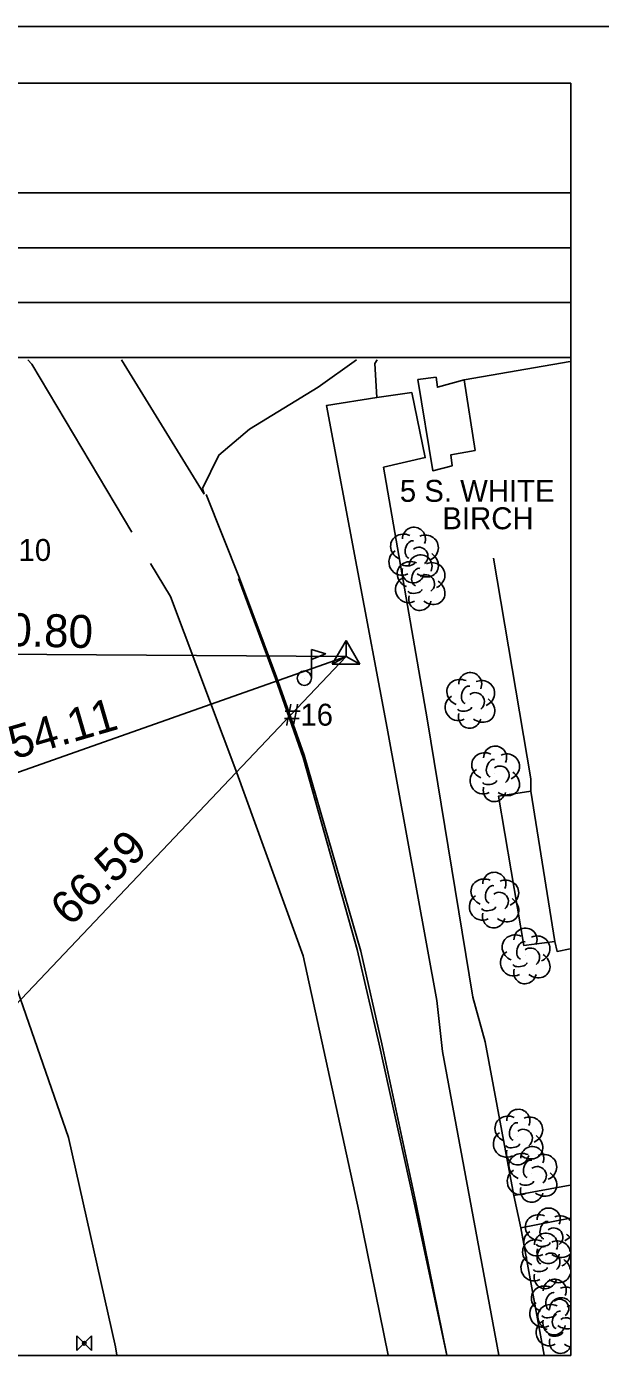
# Model space of a CAD drawing. Extents: x 1603676 to 1604316, y 320315 to 320735.
# Drawn here: x 1603771.3 to 1603823.6, y 320487.1 to 320608.2 of the extents above; entities that cross this region are included whole.
import ezdxf

# ---------------------------------------------------------------- set-up
doc = ezdxf.new("R2010")
doc.units = 0
for name, color, linetype in [('CPSM', 7, 'Continuous'), ('Default', 7, 'Continuous'), ('L_C', 7, 'Continuous'), ('LBC', 7, 'Continuous'), ('LBF', 7, 'Continuous'), ('LDEFAULT', 7, 'Continuous'), ('LMB', 7, 'Continuous'), ('LSH', 7, 'Continuous'), ('LTD', 7, 'Continuous'), ('NBL1', 7, 'Continuous'), ('PET', 7, 'Continuous'), ('PSP', 7, 'Continuous'), ('RC', 7, 'Continuous'), ('RSW', 7, 'Continuous'), ('U_C', 7, 'Continuous'), ('UWV', 7, 'Continuous')]:
    doc.layers.add(name, color=color, linetype=linetype)

msp = doc.modelspace()

# ---------------------------------------------------------------- linework, layer by layer
at = {"layer": 'CPSM'}
for p, q in [((1603799.17, 320550.09), (1603800.42, 320552.25)), ((1603801.67, 320550.09), (1603800.42, 320552.25)), ((1603800.42, 320550.81), (1603800.42, 320552.25)), ((1603799.17, 320550.09), (1603800.42, 320550.81)), ((1603799.17, 320550.09), (1603801.67, 320550.09)), ((1603800.42, 320550.81), (1603800.42, 320550.81)), ((1603800.42, 320550.81), (1603801.67, 320550.09))]:
    msp.add_line(p, q, dxfattribs=at)
at = {"layer": 'LBC'}
msp.add_lwpolyline([(1603820.87, 320524.14), (1603819.67, 320523.9), (1603819.46, 320524.82), (1603817.27, 320538.51), (1603817.28, 320539.65)], dxfattribs=at)
at = {"layer": 'LBF'}
for points in [[(1603812.2, 320569.59), (1603811.2, 320576.02), (1603820.87, 320577.68)], [(1603812.2, 320569.59), (1603809.98, 320569.17), (1603810.09, 320568.19), (1603808.33, 320567.74), (1603806.98, 320576.04), (1603808.64, 320576.26), (1603808.76, 320575.34), (1603811.2, 320576.02)], [(1603817.28, 320539.65), (1603813.86, 320559.76)], [(1603819.46, 320524.82), (1603816.65, 320524.43), (1603814.33, 320538.07), (1603817.27, 320538.51)]]:
    msp.add_lwpolyline(points, dxfattribs=at)
at = {"layer": 'LDEFAULT'}
for q in [(1603739.62, 320551.21), (1603749.41, 320532.76), (1603754.59, 320502.47)]:
    msp.add_line((1603800.42, 320550.81), q, dxfattribs=at)
at = {"layer": 'LMB'}
for p, q in [((1603797.27, 320551.42), (1603798.57, 320551.04)), ((1603797.28, 320548.83), (1603797.28, 320551.43)), ((1603797.28, 320550.53), (1603798.56, 320551.03)), ((1603796.62, 320548.82), (1603796.62, 320548.82))]:
    msp.add_line(p, q, dxfattribs=at)
msp.add_circle((1603796.62, 320548.82), 0.656, dxfattribs=at)
at = {"layer": 'LSH'}
for p, q in [((1603806.57, 320560.09), (1603806.57, 320560.09)), ((1603806.57, 320560.09), (1603806.57, 320560.09)), ((1603813.97, 320540.15), (1603813.97, 320540.15)), ((1603813.97, 320540.15), (1603813.97, 320540.15)), ((1603816.75, 320523.54), (1603816.75, 320523.54)), ((1603816.75, 320523.54), (1603816.75, 320523.54)), ((1603816.09, 320507.03), (1603816.09, 320507.03)), ((1603816.09, 320507.03), (1603816.09, 320507.03)), ((1603817.37, 320503.62), (1603817.37, 320503.62)), ((1603817.37, 320503.62), (1603817.37, 320503.62)), ((1603818.87, 320498.03), (1603818.87, 320498.03)), ((1603818.87, 320498.03), (1603818.87, 320498.03)), ((1603818.61, 320495.74), (1603818.61, 320495.74)), ((1603818.61, 320495.74), (1603818.61, 320495.74)), ((1603819.41, 320491.53), (1603819.41, 320491.53)), ((1603819.41, 320491.53), (1603819.41, 320491.53)), ((1603820, 320489.84), (1603820, 320489.84)), ((1603820, 320489.84), (1603820, 320489.84))]:
    msp.add_line(p, q, dxfattribs=at)
for centre, start in [((1603806.62, 320561.53), 335.5272), ((1603814.02, 320541.58), 335.5272), ((1603816.79, 320524.98), 335.5272), ((1603816.14, 320508.46), 335.5272), ((1603817.41, 320505.06), 335.5272), ((1603818.91, 320499.46), 335.5272), ((1603818.66, 320497.17), 335.5272), ((1603819.46, 320492.96), 335.5272), ((1603820.04, 320491.28), 37.9845)]:
    msp.add_arc(centre, 1.05, start, 180.9563, dxfattribs=at)
for centre, major_axis, ratio, start_param, end_param in [((1603805.78, 320560.76), (1.21, -0.51), 0.895232, 1.570796, 4.712389), ((1603806.37, 320560.55), (-0.208, -0.792), 0.645439, 3.141593, 6.283185), ((1603807.62, 320560.68), (-1.14, -0.48), 0.949671, 1.570796, 4.712389), ((1603805.49, 320559.38), (0.58, -1.04), 0.959034, 3.141593, 6.283185), ((1603807.07, 320559.93), (-0.5, 0.667), 0.989748, 3.141593, 6.283185), ((1603807.57, 320559.26), (-1.09, 0.79), 0.841452, 1.570796, 4.712389), ((1603806.57, 320558.59), (0.26, 1.06), 0.942809, 1.570796, 4.712389), ((1603806.12, 320559.34), (-0.625, -0.083), 0.423636, 0, 3.141593), ((1603813.18, 320540.82), (1.21, -0.51), 0.895232, 1.570796, 4.712389), ((1603815.02, 320540.73), (-1.14, -0.48), 0.949671, 1.570796, 4.712389), ((1603812.89, 320539.44), (0.58, -1.04), 0.959034, 3.141593, 6.283185), ((1603813.77, 320540.61), (-0.208, -0.792), 0.645439, 3.141593, 6.283185), ((1603814.47, 320539.98), (-0.5, 0.667), 0.989748, 3.141593, 6.283185), ((1603813.52, 320539.4), (-0.625, -0.083), 0.423636, 0, 3.141593), ((1603814.97, 320539.32), (-1.09, 0.79), 0.841452, 1.570796, 4.712389), ((1603813.97, 320538.65), (0.26, 1.06), 0.942809, 1.570796, 4.712389), ((1603815.95, 320524.21), (1.21, -0.51), 0.895232, 1.570796, 4.712389), ((1603816.54, 320524), (-0.208, -0.792), 0.645439, 3.141593, 6.283185), ((1603817.79, 320524.13), (-1.14, -0.48), 0.949671, 1.570796, 4.712389), ((1603815.66, 320522.84), (0.58, -1.04), 0.959034, 3.141593, 6.283185), ((1603817.25, 320523.38), (-0.5, 0.667), 0.989748, 3.141593, 6.283185), ((1603817.75, 320522.71), (-1.09, 0.79), 0.841452, 1.570796, 4.712389), ((1603816.75, 320522.04), (0.26, 1.06), 0.942809, 1.570796, 4.712389), ((1603816.29, 320522.79), (-0.625, -0.083), 0.423636, 0, 3.141593), ((1603815.3, 320507.69), (1.21, -0.51), 0.895232, 1.570796, 4.712389), ((1603817.13, 320507.61), (-1.14, -0.48), 0.949671, 1.570796, 4.712389), ((1603815.88, 320507.48), (-0.208, -0.792), 0.645439, 3.141593, 6.283185), ((1603816.59, 320506.86), (-0.5, 0.667), 0.989748, 3.141593, 6.283185), ((1603815.01, 320506.32), (0.58, -1.04), 0.959034, 3.141593, 6.283185), ((1603817.09, 320506.19), (-1.09, 0.79), 0.841452, 1.570796, 4.712389), ((1603816.09, 320505.53), (0.26, 1.06), 0.942809, 1.570796, 4.712389), ((1603815.63, 320506.28), (-0.625, -0.083), 0.423636, 0, 3.141593), ((1603816.57, 320504.29), (1.21, -0.51), 0.895232, 1.570796, 4.712389), ((1603818.41, 320504.21), (-1.14, -0.48), 0.949671, 1.570796, 4.712389), ((1603817.16, 320504.08), (-0.208, -0.792), 0.645439, 3.141593, 6.283185), ((1603817.87, 320503.46), (-0.5, 0.667), 0.989748, 3.141593, 6.283185), ((1603816.28, 320502.91), (0.58, -1.04), 0.959034, 3.141593, 6.283185), ((1603816.91, 320502.87), (-0.625, -0.083), 0.423636, 0, 3.141593), ((1603818.37, 320502.79), (-1.09, 0.79), 0.841452, 1.570796, 4.712389), ((1603817.37, 320502.12), (0.26, 1.06), 0.942809, 1.570796, 4.712389), ((1603818.07, 320498.7), (1.21, -0.51), 0.895232, 1.570796, 4.712389), ((1603818.66, 320498.49), (-0.208, -0.792), 0.645439, 3.141593, 6.283185), ((1603819.91, 320498.61), (-1.14, -0.48), 0.949671, 3.433011, 4.712389), ((1603817.78, 320497.32), (0.58, -1.04), 0.959034, 3.141593, 6.283185), ((1603819.37, 320497.86), (-0.5, 0.667), 0.989748, 3.141593, 6.283185), ((1603819.87, 320497.2), (-1.09, 0.79), 0.841452, 4.359168, 4.712389), ((1603817.82, 320496.41), (1.21, -0.51), 0.895232, 1.570796, 4.712389), ((1603818.87, 320496.53), (0.26, 1.06), 0.942809, 1.570796, 4.712389), ((1603818.4, 320496.2), (-0.208, -0.792), 0.645439, 3.141593, 6.283185), ((1603818.41, 320497.28), (-0.625, -0.083), 0.423636, 0, 3.141593), ((1603819.65, 320496.32), (-1.14, -0.48), 0.949671, 2.89195, 4.712389), ((1603819.91, 320498.61), (-1.14, -0.48), 0.949671, 1.570796, 2.085751), ((1603817.53, 320495.03), (0.58, -1.04), 0.959034, 3.141593, 6.283185), ((1603819.11, 320495.57), (-0.5, 0.667), 0.989748, 3.141593, 6.283185), ((1603819.87, 320497.2), (-1.09, 0.79), 0.841452, 1.570796, 3.022033), ((1603819.65, 320496.32), (-1.14, -0.48), 0.949671, 1.570796, 2.626812), ((1603819.61, 320494.91), (-1.09, 0.79), 0.841452, 3.854989, 4.712389), ((1603818.61, 320494.24), (0.26, 1.06), 0.942809, 1.570796, 4.712389), ((1603818.15, 320494.99), (-0.625, -0.083), 0.423636, 0, 3.141593), ((1603819.61, 320494.91), (-1.09, 0.79), 0.841452, 1.570796, 3.526212), ((1603818.62, 320492.2), (1.21, -0.51), 0.895232, 1.570796, 4.712389), ((1603820.45, 320492.11), (-1.14, -0.48), 0.949671, 3.985149, 4.712389), ((1603819.2, 320491.99), (-0.208, -0.792), 0.645439, 3.141593, 6.283185), ((1603819.91, 320491.36), (-0.5, 0.667), 0.989748, 3.141593, 6.283185), ((1603818.33, 320490.82), (0.58, -1.04), 0.959034, 3.141593, 6.283185), ((1603819.21, 320490.51), (1.21, -0.51), 0.895232, 1.570796, 4.712389), ((1603818.95, 320490.78), (-0.625, -0.083), 0.423636, 0, 3.141593), ((1603819.79, 320490.3), (-0.208, -0.792), 0.645439, 3.141593, 6.283185), ((1603821.04, 320490.43), (-1.14, -0.48), 0.949671, 4.46847, 4.712389), ((1603818.91, 320489.13), (0.58, -1.04), 0.959034, 3.141593, 6.283185), ((1603819.41, 320490.03), (0.26, 1.06), 0.942809, 1.570796, 4.712389), ((1603820.41, 320490.7), (-1.09, 0.79), 0.841452, 1.570796, 2.485909), ((1603820.5, 320489.68), (-0.5, 0.667), 0.989748, 5.168439, 6.283185), ((1603820, 320488.34), (0.26, 1.06), 0.942809, 1.570796, 4.402912), ((1603819.54, 320489.09), (-0.625, -0.083), 0.423636, 0, 3.141593), ((1603821, 320489.01), (-1.09, 0.79), 0.841452, 1.570796, 2.019377)]:
    msp.add_ellipse(centre, major_axis=major_axis, ratio=ratio, start_param=start_param, end_param=end_param, dxfattribs=at)
at = {"layer": 'LTD'}
for p, q in [((1603807.17, 320557.58), (1603807.17, 320557.58)), ((1603807.17, 320557.58), (1603807.17, 320557.58)), ((1603811.71, 320546.84), (1603811.71, 320546.84)), ((1603811.71, 320546.84), (1603811.71, 320546.84)), ((1603813.9, 320528.64), (1603813.9, 320528.64)), ((1603813.9, 320528.64), (1603813.9, 320528.64))]:
    msp.add_line(p, q, dxfattribs=at)
for centre in [(1603807.22, 320559.02), (1603811.75, 320548.28), (1603813.95, 320530.07)]:
    msp.add_arc(centre, 1.05, 335.5272, 180.9563, dxfattribs=at)
for centre, major_axis, ratio, start_param, end_param in [((1603806.38, 320558.25), (1.21, -0.51), 0.895232, 1.570796, 4.712389), ((1603806.96, 320558.04), (-0.208, -0.792), 0.645439, 3.141593, 6.283185), ((1603808.21, 320558.17), (-1.14, -0.48), 0.949671, 1.570796, 4.712389), ((1603806.09, 320556.87), (0.58, -1.04), 0.959034, 3.141593, 6.283185), ((1603807.67, 320557.42), (-0.5, 0.667), 0.989748, 3.141593, 6.283185), ((1603808.17, 320556.75), (-1.09, 0.79), 0.841452, 1.570796, 4.712389), ((1603807.17, 320556.08), (0.26, 1.06), 0.942809, 1.570796, 4.712389), ((1603806.71, 320556.83), (-0.625, -0.083), 0.423636, 0, 3.141593), ((1603810.91, 320547.51), (1.21, -0.51), 0.895232, 1.570796, 4.712389), ((1603811.5, 320547.3), (-0.208, -0.792), 0.645439, 3.141593, 6.283185), ((1603812.75, 320547.42), (-1.14, -0.48), 0.949671, 1.570796, 4.712389), ((1603810.62, 320546.13), (0.58, -1.04), 0.959034, 3.141593, 6.283185), ((1603812.21, 320546.67), (-0.5, 0.667), 0.989748, 3.141593, 6.283185), ((1603812.71, 320546.01), (-1.09, 0.79), 0.841452, 1.570796, 4.712389), ((1603811.71, 320545.34), (0.26, 1.06), 0.942809, 1.570796, 4.712389), ((1603811.25, 320546.09), (-0.625, -0.083), 0.423636, 0, 3.141593), ((1603813.11, 320529.31), (1.21, -0.51), 0.895232, 1.570796, 4.712389), ((1603813.69, 320529.1), (-0.208, -0.792), 0.645439, 3.141593, 6.283185), ((1603814.94, 320529.22), (-1.14, -0.48), 0.949671, 1.570796, 4.712389), ((1603812.82, 320527.93), (0.58, -1.04), 0.959034, 3.141593, 6.283185), ((1603814.4, 320528.47), (-0.5, 0.667), 0.989748, 3.141593, 6.283185), ((1603814.9, 320527.81), (-1.09, 0.79), 0.841452, 1.570796, 4.712389), ((1603813.9, 320527.14), (0.26, 1.06), 0.942809, 1.570796, 4.712389), ((1603813.44, 320527.89), (-0.625, -0.083), 0.423636, 0, 3.141593)]:
    msp.add_ellipse(centre, major_axis=major_axis, ratio=ratio, start_param=start_param, end_param=end_param, dxfattribs=at)
at = {"layer": 'NBL1'}
for p, q in [((1603675.93, 320608.23), (1604315.93, 320608.23)), ((1603820.92, 320593.07), (1603710.92, 320593.07)), ((1603820.92, 320588.07), (1603710.92, 320588.07)), ((1603820.92, 320583.07), (1603710.92, 320583.07)), ((1603820.92, 320578.07), (1603710.92, 320578.07))]:
    msp.add_line(p, q, dxfattribs=at)
msp.add_lwpolyline([(1603710.92, 320487.07), (1603820.92, 320487.07), (1603820.92, 320603.07), (1603710.92, 320603.07)], close=True, dxfattribs=at)
at = {"layer": 'PET'}
for points in [[(1603780.89, 320562.14), (1603771.75, 320577.45), (1603771.41, 320577.86)], [(1603787.34, 320566.12), (1603788.83, 320569.16), (1603791.61, 320571.51), (1603797.89, 320575.34), (1603801.37, 320577.86)], [(1603779.52, 320487.09), (1603779.41, 320487.86), (1603775.12, 320506.94), (1603766.54, 320531.56), (1603758.05, 320550.82), (1603753.68, 320559)], [(1603804.28, 320487.09), (1603801.59, 320500.24), (1603796.52, 320523.49), (1603790.47, 320540.2), (1603784.4, 320556.26), (1603782.6, 320559.29)]]:
    msp.add_lwpolyline(points, dxfattribs=at)
at = {"layer": 'PSP'}
for points in [[(1603779.95, 320577.86), (1603787.49, 320565.6)], [(1603787.49, 320565.6), (1603787.34, 320566.12)], [(1603809.61, 320487.09), (1603806.65, 320500.98), (1603803.43, 320515.45), (1603801.44, 320524.07), (1603796.51, 320541.6), (1603793.98, 320548.79), (1603790.61, 320557.92)]]:
    msp.add_lwpolyline(points, dxfattribs=at)
at = {"layer": 'RC'}
msp.add_lwpolyline([(1603809.62, 320487.09), (1603806.8, 320501.01), (1603803.7, 320515.49), (1603801.76, 320523.94), (1603796.61, 320541.79), (1603794.08, 320548.9), (1603790.71, 320557.93), (1603787.68, 320565.58)], dxfattribs=at)
at = {"layer": 'RSW'}
for points in [[(1603803.24, 320574.42), (1603803.06, 320577.51), (1603803.25, 320577.86)], [(1603814.35, 320487.09), (1603809.22, 320514.78), (1603808.7, 320519.42), (1603804.16, 320544.27), (1603798.64, 320573.67), (1603803.24, 320574.42), (1603806.42, 320574.86), (1603807.64, 320568.94), (1603803.85, 320568.07)], [(1603818.5, 320487.09), (1603816.38, 320498.69), (1603815.73, 320501.65), (1603813.12, 320515.67), (1603812, 320519.72), (1603807.81, 320545.12), (1603803.85, 320568.07)], [(1603820.87, 320502.58), (1603815.73, 320501.65)], [(1603816.38, 320498.69), (1603820.87, 320499.59)]]:
    msp.add_lwpolyline(points, dxfattribs=at)
at = {"layer": 'UWV'}
for p, q in [((1603775.88, 320488.84), (1603777.21, 320487.51)), ((1603777.21, 320488.84), (1603775.88, 320487.51))]:
    msp.add_line(p, q, dxfattribs=at)
for points in [[(1603775.88, 320488.84), (1603775.88, 320487.51)], [(1603777.21, 320487.51), (1603777.21, 320488.84)]]:
    msp.add_lwpolyline(points, dxfattribs=at)
msp.add_circle((1603776.54, 320488.18), 0.167, dxfattribs=at)

# ---------------------------------------------------------------- texts
at = {"layer": 'Default'}
for s, rotation, p in [('60.80', 358.4195, (1603767.27, 320551.83)), ('54.11', 16.2347, (1603770.16, 320541.41)), ('66.59', 44.0662, (1603775.26, 320526.1))]:
    msp.add_text(s, height=3, rotation=rotation, dxfattribs=at).set_placement(p)
at = {"layer": 'L_C'}
for s, p in [('5 S. WHITE ', (1603805.33, 320564.9)), ('BIRCH', (1603809.21, 320562.4)), ('#16', (1603794.77, 320544.49))]:
    msp.add_text(s, height=2, dxfattribs=at).set_placement(p)
at = {"layer": 'U_C'}
msp.add_text('#9/72/9500/6.5/9510', height=2, dxfattribs=at).set_placement((1603748.99, 320559.51))

doc.saveas('drawing.dxf')
